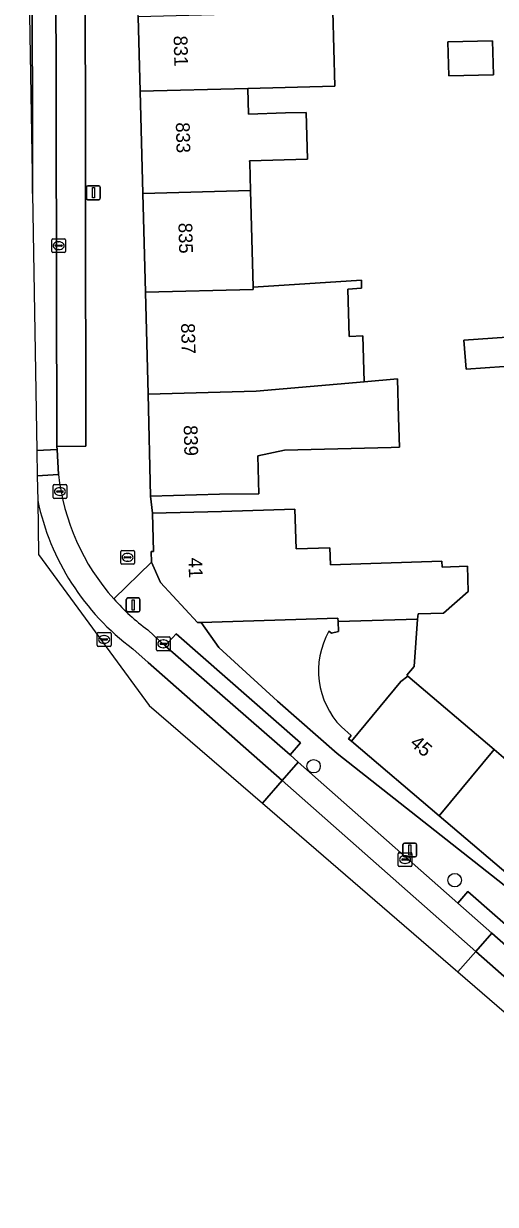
# Model space of a CAD drawing. Extents: x 162073 to 163043, y 381818 to 382561.
# Drawn here: x 162092.6 to 162126.8, y 382154 to 382239.5 of the extents above; entities that cross this region are included whole.
import ezdxf

# ---------------------------------------------------------------- set-up
doc = ezdxf.new("R2010")
doc.units = 0
for name, color, linetype in [('IMGEO_Boom', 7, 'Continuous'), ('IMGEO_Brandkraan', 7, 'Continuous'), ('IMGEO_Erf', 7, 'Continuous'), ('IMGEO_Kolk', 7, 'Continuous'), ('IMGEO_Lichtmast', 7, 'Continuous'), ('IMGEO_Pand', 7, 'Continuous'), ('IMGEO_Pand_nummerreeks', 7, 'Continuous'), ('IMGEO_Parkeervlak_open', 7, 'Continuous'), ('IMGEO_Rijbaan_lokaal_gesloten', 7, 'Continuous'), ('IMGEO_Rijbaan_lokaal_open', 7, 'Continuous'), ('IMGEO_Rioolput', 7, 'Continuous'), ('IMGEO_Voetpad_open', 7, 'Continuous')]:
    doc.layers.add(name, color=color, linetype=linetype)

msp = doc.modelspace()

# ---------------------------------------------------------------- linework, layer by layer
at = {"layer": 'IMGEO_Boom'}
for centre in [(162113.59, 382185.761), (162123.817, 382177.516)]:
    msp.add_circle(centre, 0.489, dxfattribs=at)
at = {"layer": 'IMGEO_Brandkraan'}
for p, q in [((162099.618, 382200.458), (162099.618, 382201.31)), ((162099.693, 382201.384), (162100.545, 382201.384)), ((162099.877, 382200.878), (162099.877, 382200.89)), ((162100.315, 382200.841), (162099.917, 382200.841)), ((162099.92, 382200.927), (162100.318, 382200.927)), ((162100.129, 382200.604), (162100.104, 382200.604)), ((162100.106, 382201.164), (162100.131, 382201.164)), ((162100.361, 382200.89), (162100.361, 382200.878)), ((162100.619, 382201.31), (162100.619, 382200.458)), ((162100.545, 382200.384), (162099.693, 382200.384))]:
    msp.add_line(p, q, dxfattribs=at)
for points in [[(162099.618, 382200.458), (162099.618, 382201.31)], [(162099.693, 382201.384), (162100.545, 382201.384)], [(162100.619, 382201.31), (162100.619, 382200.458)], [(162100.545, 382200.384), (162099.693, 382200.384)]]:
    msp.add_lwpolyline(points, dxfattribs=at)
for centre, radius, start, end in [((162099.695, 382201.308), 0.0765, 91.55205, 178.44795), ((162099.695, 382201.308), 0.0765, 91.55205, 178.44795), ((162099.917, 382200.887), 0.0403, 85.87752, 175.75265), ((162099.914, 382200.877), 0.0366, 178.93798, 274.71019), ((162100.318, 382200.884), 0.043, 264.86636, 352.45326), ((162100.322, 382200.889), 0.0386, 1.73085, 96.63898), ((162100.543, 382201.308), 0.0765, 1.55205, 88.44795), ((162100.543, 382201.308), 0.0765, 1.55205, 88.44795), ((162099.695, 382200.46), 0.0765, 181.55205, 268.44795), ((162099.695, 382200.46), 0.0765, 181.55205, 268.44795), ((162100.543, 382200.46), 0.0765, 271.55205, 358.44795), ((162100.543, 382200.46), 0.0765, 271.55205, 358.44795)]:
    msp.add_arc(centre, radius, start, end, dxfattribs=at)
for centre, major_axis, ratio, start_param, end_param in [((162100.105, 382200.884), (-0.387, 0.002), 0.722429, 4.712389, 7.853982), ((162100.13, 382200.884), (-0.39, 0.002), 0.717154, 1.570796, 4.712389)]:
    msp.add_ellipse(centre, major_axis=major_axis, ratio=ratio, start_param=start_param, end_param=end_param, dxfattribs=at)
at = {"layer": 'IMGEO_Erf'}
for points in [[(162114.982, 382240.388), (162115.121, 382234.987), (162108.82, 382234.834), (162108.873, 382232.978), (162111.548, 382233.054), (162113.051, 382233.097), (162113.148, 382229.701), (162108.958, 382229.582), (162108.961, 382229.475), (162109.019, 382227.44), (162109.22, 382220.433), (162117.054, 382220.951), (162117.069, 382220.362), (162116.079, 382220.309), (162116.159, 382216.882), (162117.159, 382216.908), (162117.245, 382213.599), (162119.68, 382213.815), (162119.753, 382211.001), (162119.809, 382208.856), (162119.208, 382208.841), (162111.491, 382208.642), (162109.564, 382208.226), (162109.636, 382205.482), (162106.786, 382205.446), (162101.788, 382205.303), (162101.912, 382204.071), (162106.91, 382204.214), (162112.238, 382204.367), (162112.32, 382201.493), (162114.769, 382201.573), (162114.81, 382200.334), (162122.886, 382200.599), (162122.9, 382200.172), (162124.742, 382200.233), (162124.802, 382198.405), (162123.009, 382196.852), (162121.156, 382196.796), (162121.126, 382196.404), (162120.867, 382192.984), (162120.336, 382192.358), (162120.417, 382192.289), (162126.683, 382186.968), (162128.881, 382185.102)], [(162114.707, 382195.536), (162114.894, 382195.385), (162115.389, 382195.506), (162115.361, 382196.228), (162115.351, 382196.472), (162105.452, 382196.17), (162106.723, 382194.356), (162110.979, 382190.462), (162115.288, 382186.678), (162128.205, 382176.536), (162128.654, 382177.108), (162122.692, 382182.171), (162116.33, 382187.574), (162116.118, 382187.754), (162116.308, 382187.99), (162115.612, 382188.605)]]:
    msp.add_lwpolyline(points, dxfattribs=at)
for points in [[(162126.619, 382235.824), (162123.389, 382235.74), (162123.326, 382238.193), (162126.556, 382238.277)], [(162128.77, 382214.806), (162124.636, 382214.51), (162124.487, 382216.597), (162128.621, 382216.892)]]:
    msp.add_lwpolyline(points, close=True, dxfattribs=at)
msp.add_arc((162119.709, 382192.665), 5.768, 150.14404, 224.73433, dxfattribs=at)
at = {"layer": 'IMGEO_Kolk'}
for p, q in [((162094.622, 382223.019), (162094.622, 382223.871)), ((162094.697, 382223.945), (162095.549, 382223.945)), ((162095.11, 382223.725), (162095.135, 382223.725)), ((162095.623, 382223.871), (162095.623, 382223.019)), ((162095.549, 382222.945), (162094.697, 382222.945)), ((162094.881, 382223.439), (162094.881, 382223.451)), ((162095.319, 382223.402), (162094.921, 382223.402)), ((162094.924, 382223.488), (162095.322, 382223.488)), ((162095.133, 382223.165), (162095.108, 382223.165)), ((162095.365, 382223.451), (162095.365, 382223.439)), ((162094.716, 382205.22), (162094.716, 382206.072)), ((162094.791, 382206.146), (162095.643, 382206.146)), ((162095.018, 382205.689), (162095.416, 382205.689)), ((162095.204, 382205.926), (162095.229, 382205.926)), ((162095.717, 382206.072), (162095.717, 382205.22)), ((162095.643, 382205.146), (162094.791, 382205.146)), ((162094.975, 382205.64), (162094.975, 382205.652)), ((162095.413, 382205.603), (162095.015, 382205.603)), ((162095.227, 382205.366), (162095.202, 382205.366)), ((162095.459, 382205.652), (162095.459, 382205.64)), ((162102.206, 382194.195), (162102.206, 382195.047)), ((162102.281, 382195.121), (162103.133, 382195.121)), ((162102.465, 382194.615), (162102.465, 382194.627)), ((162102.903, 382194.578), (162102.505, 382194.578)), ((162102.508, 382194.664), (162102.906, 382194.664)), ((162102.694, 382194.901), (162102.719, 382194.901)), ((162102.949, 382194.627), (162102.949, 382194.615)), ((162103.207, 382195.047), (162103.207, 382194.195)), ((162103.133, 382194.121), (162102.281, 382194.121)), ((162102.717, 382194.341), (162102.692, 382194.341)), ((162119.719, 382178.578), (162119.719, 382179.43)), ((162119.794, 382179.504), (162120.646, 382179.504)), ((162120.207, 382179.284), (162120.232, 382179.284)), ((162120.72, 382179.43), (162120.72, 382178.578)), ((162120.646, 382178.504), (162119.794, 382178.504)), ((162119.978, 382178.998), (162119.978, 382179.01)), ((162120.416, 382178.961), (162120.018, 382178.961)), ((162120.021, 382179.047), (162120.419, 382179.047)), ((162120.23, 382178.724), (162120.205, 382178.724)), ((162120.462, 382179.01), (162120.462, 382178.998))]:
    msp.add_line(p, q, dxfattribs=at)
for points in [[(162094.622, 382223.019), (162094.622, 382223.871)], [(162094.697, 382223.945), (162095.549, 382223.945)], [(162095.623, 382223.871), (162095.623, 382223.019)], [(162095.549, 382222.945), (162094.697, 382222.945)], [(162094.716, 382205.22), (162094.716, 382206.072)], [(162094.791, 382206.146), (162095.643, 382206.146)], [(162095.717, 382206.072), (162095.717, 382205.22)], [(162095.643, 382205.146), (162094.791, 382205.146)], [(162102.206, 382194.195), (162102.206, 382195.047)], [(162102.281, 382195.121), (162103.133, 382195.121)], [(162103.207, 382195.047), (162103.207, 382194.195)], [(162103.133, 382194.121), (162102.281, 382194.121)], [(162119.719, 382178.578), (162119.719, 382179.43)], [(162119.794, 382179.504), (162120.646, 382179.504)], [(162120.72, 382179.43), (162120.72, 382178.578)], [(162120.646, 382178.504), (162119.794, 382178.504)]]:
    msp.add_lwpolyline(points, dxfattribs=at)
for centre, radius, start, end in [((162094.699, 382223.869), 0.0765, 91.55205, 178.44795), ((162094.699, 382223.869), 0.0765, 91.55205, 178.44795), ((162095.547, 382223.869), 0.0765, 1.55205, 88.44795), ((162095.547, 382223.869), 0.0765, 1.55205, 88.44795), ((162094.699, 382223.021), 0.0765, 181.55205, 268.44795), ((162094.699, 382223.021), 0.0765, 181.55205, 268.44795), ((162094.921, 382223.448), 0.0403, 85.87752, 175.75265), ((162094.918, 382223.438), 0.0366, 178.93798, 274.71019), ((162095.322, 382223.445), 0.043, 264.86636, 352.45326), ((162095.326, 382223.45), 0.0386, 1.73085, 96.63898), ((162095.547, 382223.021), 0.0765, 271.55205, 358.44795), ((162095.547, 382223.021), 0.0765, 271.55205, 358.44795), ((162094.793, 382206.07), 0.0765, 91.55205, 178.44795), ((162094.793, 382206.07), 0.0765, 91.55205, 178.44795), ((162095.015, 382205.649), 0.0403, 85.87752, 175.75265), ((162095.42, 382205.651), 0.0386, 1.73085, 96.63898), ((162095.641, 382206.07), 0.0765, 1.55205, 88.44795), ((162095.641, 382206.07), 0.0765, 1.55205, 88.44795), ((162094.793, 382205.222), 0.0765, 181.55205, 268.44795), ((162094.793, 382205.222), 0.0765, 181.55205, 268.44795), ((162095.012, 382205.639), 0.0366, 178.93798, 274.71019), ((162095.416, 382205.646), 0.043, 264.86636, 352.45326), ((162095.641, 382205.222), 0.0765, 271.55205, 358.44795), ((162095.641, 382205.222), 0.0765, 271.55205, 358.44795), ((162102.283, 382195.045), 0.0765, 91.55205, 178.44795), ((162102.283, 382195.045), 0.0765, 91.55205, 178.44795), ((162102.505, 382194.624), 0.0403, 85.87752, 175.75265), ((162102.502, 382194.614), 0.0366, 178.93798, 274.71019), ((162102.906, 382194.621), 0.043, 264.86636, 352.45326), ((162102.91, 382194.626), 0.0386, 1.73085, 96.63898), ((162103.131, 382195.045), 0.0765, 1.55205, 88.44795), ((162103.131, 382195.045), 0.0765, 1.55205, 88.44795), ((162102.283, 382194.197), 0.0765, 181.55205, 268.44795), ((162102.283, 382194.197), 0.0765, 181.55205, 268.44795), ((162103.131, 382194.197), 0.0765, 271.55205, 358.44795), ((162103.131, 382194.197), 0.0765, 271.55205, 358.44795), ((162119.796, 382179.428), 0.0765, 91.55205, 178.44795), ((162119.796, 382179.428), 0.0765, 91.55205, 178.44795), ((162120.644, 382179.428), 0.0765, 1.55205, 88.44795), ((162120.644, 382179.428), 0.0765, 1.55205, 88.44795), ((162119.796, 382178.58), 0.0765, 181.55205, 268.44795), ((162119.796, 382178.58), 0.0765, 181.55205, 268.44795), ((162120.018, 382179.007), 0.0403, 85.87752, 175.75265), ((162120.015, 382178.997), 0.0366, 178.93798, 274.71019), ((162120.419, 382179.004), 0.043, 264.86636, 352.45326), ((162120.423, 382179.009), 0.0386, 1.73085, 96.63898), ((162120.644, 382178.58), 0.0765, 271.55205, 358.44795), ((162120.644, 382178.58), 0.0765, 271.55205, 358.44795)]:
    msp.add_arc(centre, radius, start, end, dxfattribs=at)
for centre, major_axis, ratio, start_param, end_param in [((162095.109, 382223.445), (-0.387, 0.002), 0.722429, 4.712389, 7.853982), ((162095.134, 382223.445), (-0.39, 0.002), 0.717154, 1.570796, 4.712389), ((162095.203, 382205.646), (-0.387, 0.002), 0.722429, 4.712389, 7.853982), ((162095.228, 382205.646), (-0.39, 0.002), 0.717154, 1.570796, 4.712389), ((162102.693, 382194.621), (-0.387, 0.002), 0.722429, 4.712389, 7.853982), ((162102.718, 382194.621), (-0.39, 0.002), 0.717154, 1.570796, 4.712389), ((162120.206, 382179.004), (-0.387, 0.002), 0.722429, 4.712389, 7.853982), ((162120.231, 382179.004), (-0.39, 0.002), 0.717154, 1.570796, 4.712389)]:
    msp.add_ellipse(centre, major_axis=major_axis, ratio=ratio, start_param=start_param, end_param=end_param, dxfattribs=at)
at = {"layer": 'IMGEO_Lichtmast'}
for p, q in [((162097.142, 382226.876), (162097.142, 382227.676)), ((162097.142, 382227.676), (162097.142, 382226.876)), ((162097.242, 382227.776), (162098.032, 382227.776)), ((162098.032, 382227.776), (162097.242, 382227.776)), ((162098.132, 382227.676), (162098.132, 382226.876)), ((162098.132, 382226.876), (162098.132, 382227.676)), ((162098.032, 382226.776), (162097.242, 382226.776)), ((162097.242, 382226.776), (162098.032, 382226.776)), ((162100.023, 382197.042), (162100.023, 382197.842)), ((162100.023, 382197.842), (162100.023, 382197.042)), ((162100.123, 382197.942), (162100.913, 382197.942)), ((162100.913, 382197.942), (162100.123, 382197.942)), ((162101.013, 382197.842), (162101.013, 382197.042)), ((162101.013, 382197.042), (162101.013, 382197.842)), ((162100.913, 382196.942), (162100.123, 382196.942)), ((162100.123, 382196.942), (162100.913, 382196.942)), ((162120.069, 382179.303), (162120.069, 382180.103)), ((162120.069, 382180.103), (162120.069, 382179.303)), ((162120.169, 382180.203), (162120.959, 382180.203)), ((162120.959, 382180.203), (162120.169, 382180.203)), ((162121.059, 382180.103), (162121.059, 382179.303)), ((162121.059, 382179.303), (162121.059, 382180.103)), ((162120.959, 382179.203), (162120.169, 382179.203)), ((162120.169, 382179.203), (162120.959, 382179.203))]:
    msp.add_line(p, q, dxfattribs=at)
for points in [[(162097.562, 382227.651), (162097.712, 382227.651), (162097.712, 382226.901), (162097.562, 382226.901), (162097.562, 382227.651)], [(162100.443, 382197.817), (162100.593, 382197.817), (162100.593, 382197.067), (162100.443, 382197.067), (162100.443, 382197.817)], [(162120.489, 382180.078), (162120.639, 382180.078), (162120.639, 382179.328), (162120.489, 382179.328), (162120.489, 382180.078)]]:
    msp.add_lwpolyline(points, dxfattribs=at)
for centre, start, end in [((162097.242, 382227.676), 90, 180), ((162097.242, 382227.676), 90, 180), ((162098.032, 382227.676), 0, 90), ((162098.032, 382227.676), 360, 90), ((162097.242, 382226.876), 180, 270), ((162097.242, 382226.876), 180, 270), ((162098.032, 382226.876), 270, 0), ((162098.032, 382226.876), 270, 0), ((162100.123, 382197.842), 90, 180), ((162100.123, 382197.842), 90, 180), ((162100.913, 382197.842), 0, 90), ((162100.913, 382197.842), 360, 90), ((162100.123, 382197.042), 180, 270), ((162100.123, 382197.042), 180, 270), ((162100.913, 382197.042), 270, 0), ((162100.913, 382197.042), 270, 0), ((162120.169, 382180.103), 90, 180), ((162120.169, 382180.103), 90, 180), ((162120.959, 382180.103), 0, 90), ((162120.959, 382180.103), 360, 90), ((162120.169, 382179.303), 180, 270), ((162120.169, 382179.303), 180, 270), ((162120.959, 382179.303), 270, 0), ((162120.959, 382179.303), 270, 0)]:
    msp.add_arc(centre, 0.1, start, end, dxfattribs=at)
at = {"layer": 'IMGEO_Pand'}
for points in [[(162108.82, 382234.834), (162115.121, 382234.987), (162114.982, 382240.388), (162114.674, 382240.38), (162100.891, 382240.002), (162101.03, 382234.622)], [(162126.619, 382235.824), (162126.556, 382238.277), (162123.326, 382238.193), (162123.389, 382235.74)], [(162113.051, 382233.097), (162111.548, 382233.054), (162108.873, 382232.978), (162108.82, 382234.834), (162101.03, 382234.622), (162101.221, 382227.228), (162109.019, 382227.44), (162108.961, 382229.475), (162108.958, 382229.582), (162113.148, 382229.701)], [(162109.019, 382227.44), (162101.221, 382227.228), (162101.406, 382220.07), (162109.224, 382220.283), (162109.22, 382220.433)], [(162117.159, 382216.908), (162116.159, 382216.882), (162116.079, 382220.309), (162117.069, 382220.362), (162117.054, 382220.951), (162109.22, 382220.433), (162109.224, 382220.283), (162101.406, 382220.07), (162101.597, 382212.694), (162109.441, 382212.907), (162117.245, 382213.599)], [(162124.636, 382214.51), (162128.77, 382214.806), (162128.621, 382216.892), (162124.487, 382216.597)], [(162119.753, 382211.001), (162119.68, 382213.815), (162117.245, 382213.599), (162109.441, 382212.907), (162101.597, 382212.694), (162101.788, 382205.303), (162106.786, 382205.446), (162109.636, 382205.482), (162109.564, 382208.226), (162111.491, 382208.642), (162119.208, 382208.841), (162119.809, 382208.856)], [(162122.886, 382200.599), (162114.81, 382200.334), (162114.769, 382201.573), (162112.32, 382201.493), (162112.238, 382204.367), (162106.91, 382204.214), (162101.912, 382204.071), (162101.99, 382201.313), (162101.832, 382201.309), (162101.855, 382200.535), (162102.489, 382199.064), (162105.192, 382196.162), (162105.452, 382196.17), (162115.351, 382196.472), (162115.361, 382196.228), (162121.126, 382196.404), (162121.156, 382196.796), (162123.009, 382196.852), (162124.802, 382198.405), (162124.742, 382200.233), (162122.9, 382200.172)], [(162116.33, 382187.574), (162122.692, 382182.171), (162126.683, 382186.968), (162120.417, 382192.289), (162119.922, 382191.893)], [(162122.692, 382182.171), (162128.654, 382177.108), (162132.693, 382181.866), (162128.881, 382185.102), (162126.683, 382186.968)]]:
    msp.add_lwpolyline(points, close=True, dxfattribs=at)
msp.add_lwpolyline([(162115.612, 382188.605), (162116.308, 382187.99), (162116.118, 382187.754), (162116.33, 382187.574), (162119.922, 382191.893), (162120.417, 382192.289), (162120.336, 382192.358), (162120.867, 382192.984), (162121.126, 382196.404), (162115.361, 382196.228), (162115.389, 382195.506), (162114.894, 382195.385), (162114.707, 382195.536)], dxfattribs=at)
msp.add_arc((162119.709, 382192.665), 5.768, 150.14404, 224.73433, dxfattribs=at)
at = {"layer": 'IMGEO_Parkeervlak_open'}
for points in [[(162094.896, 382256.77), (162095.001, 382208.911)], [(162095.001, 382208.911), (162097.085, 382208.93), (162097.038, 382245.779)]]:
    msp.add_lwpolyline(points, dxfattribs=at)
at = {"layer": 'IMGEO_Rijbaan_lokaal_gesloten'}
for points in [[(162093.544, 382208.615), (162095.014, 382208.683), (162095.001, 382208.911), (162094.896, 382256.77), (162094.884, 382264.048), (162093.177, 382264.048), (162093.226, 382227.227)], [(162112.473, 382186.067), (162111.312, 382184.731), (162125.354, 382172.361), (162126.507, 382173.673), (162124.041, 382175.842)], [(162180.708, 382125.942), (162167.996, 382137.104), (162167.885, 382137.201), (162167.101, 382137.877), (162163.514, 382141.043), (162162.557, 382141.907), (162133.933, 382167.137), (162132.408, 382168.485), (162126.507, 382173.673), (162125.354, 382172.361), (162179.272, 382124.864), (162197.645, 382110.646), (162198.731, 382112.02), (162198.53, 382112.194)]]:
    msp.add_lwpolyline(points, close=True, dxfattribs=at)
for points in [[(162095.114, 382206.885), (162093.575, 382206.795), (162093.606, 382205.009)], [(162100.495, 382194.267), (162101.615, 382193.273), (162111.312, 382184.731), (162112.473, 382186.067), (162111.891, 382186.581), (162102.844, 382194.469), (162102.427, 382194.84), (162101.573, 382195.633)]]:
    msp.add_lwpolyline(points, dxfattribs=at)
for centre, radius, start, end in [((162111.188, 382208.632), 16.169, 186.20126, 221.72725), ((162111.15, 382208.68), 17.924, 191.81777, 233.52627), ((162111.195, 382208.642), 16.181, 221.73864, 233.51193)]:
    msp.add_arc(centre, radius, start, end, dxfattribs=at)
at = {"layer": 'IMGEO_Rijbaan_lokaal_open'}
for points in [[(162093.226, 382227.227), (162093.177, 382264.048), (162094.884, 382264.048), (162094.885, 382264.932), (162093.137, 382264.876), (162092.582, 382264.872), (162092.784, 382253.072), (162093.226, 382227.227)], [(162093.575, 382206.795), (162095.114, 382206.885), (162095.014, 382208.683), (162093.544, 382208.615), (162093.575, 382206.795)], [(162093.606, 382205.009), (162093.673, 382201.086), (162101.683, 382190.161), (162109.883, 382183.088)], [(162109.883, 382183.088), (162111.312, 382184.731), (162101.615, 382193.273), (162100.495, 382194.267)], [(162124.046, 382170.871), (162125.354, 382172.361), (162111.312, 382184.731), (162109.883, 382183.088), (162124.046, 382170.871)], [(162196.622, 382109.326), (162197.645, 382110.646), (162179.272, 382124.864), (162125.354, 382172.361), (162124.046, 382170.871), (162166.369, 382134.365), (162181.661, 382121.174), (162196.622, 382109.326)]]:
    msp.add_lwpolyline(points, dxfattribs=at)
msp.add_arc((162111.15, 382208.68), 17.924, 191.81777, 233.52627, dxfattribs=at)
at = {"layer": 'IMGEO_Rioolput'}
for p, q in [((162097.991, 382195.44), (162098.843, 382195.44)), ((162097.916, 382194.514), (162097.916, 382195.366)), ((162098.175, 382194.934), (162098.175, 382194.946)), ((162098.613, 382194.897), (162098.215, 382194.897)), ((162098.218, 382194.983), (162098.616, 382194.983)), ((162098.427, 382194.66), (162098.402, 382194.66)), ((162098.404, 382195.22), (162098.429, 382195.22)), ((162098.659, 382194.946), (162098.659, 382194.934)), ((162098.917, 382195.366), (162098.917, 382194.514)), ((162098.843, 382194.44), (162097.991, 382194.44))]:
    msp.add_line(p, q, dxfattribs=at)
for points in [[(162097.991, 382195.44), (162098.843, 382195.44)], [(162097.916, 382194.514), (162097.916, 382195.366)], [(162098.917, 382195.366), (162098.917, 382194.514)], [(162098.843, 382194.44), (162097.991, 382194.44)]]:
    msp.add_lwpolyline(points, dxfattribs=at)
for centre, radius, start, end in [((162097.993, 382195.364), 0.0765, 91.55205, 178.44795), ((162097.993, 382195.364), 0.0765, 91.55205, 178.44795), ((162098.841, 382195.364), 0.0765, 1.55205, 88.44795), ((162098.841, 382195.364), 0.0765, 1.55205, 88.44795), ((162098.215, 382194.943), 0.0403, 85.87752, 175.75265), ((162098.212, 382194.933), 0.0366, 178.93798, 274.71019), ((162098.616, 382194.94), 0.043, 264.86636, 352.45326), ((162098.62, 382194.945), 0.0386, 1.73085, 96.63898), ((162097.993, 382194.516), 0.0765, 181.55205, 268.44795), ((162097.993, 382194.516), 0.0765, 181.55205, 268.44795), ((162098.841, 382194.516), 0.0765, 271.55205, 358.44795), ((162098.841, 382194.516), 0.0765, 271.55205, 358.44795)]:
    msp.add_arc(centre, radius, start, end, dxfattribs=at)
for centre, major_axis, ratio, start_param, end_param in [((162098.403, 382194.94), (-0.387, 0.002), 0.722429, 4.712389, 7.853982), ((162098.428, 382194.94), (-0.39, 0.002), 0.717154, 1.570796, 4.712389)]:
    msp.add_ellipse(centre, major_axis=major_axis, ratio=ratio, start_param=start_param, end_param=end_param, dxfattribs=at)
at = {"layer": 'IMGEO_Voetpad_open'}
for points in [[(162099.121, 382197.87), (162101.855, 382200.535), (162101.832, 382201.309), (162101.99, 382201.313), (162101.912, 382204.071), (162101.788, 382205.303), (162101.597, 382212.694), (162101.406, 382220.07), (162101.221, 382227.228), (162101.03, 382234.622), (162100.891, 382240.002), (162100.737, 382245.969), (162100.633, 382250), (162100.463, 382256.572), (162100.29, 382263.285), (162100.136, 382269.243), (162099.774, 382283.238), (162101.824, 382283.276), (162101.939, 382286.02), (162101.97, 382292.535), (162101.962, 382297.689), (162101.954, 382300.039), (162101.931, 382301.562), (162101.986, 382343.468)], [(162095.392, 382280.819), (162096.753, 382279.402), (162096.994, 382278.768), (162097.009, 382249.05), (162098.084, 382249.034), (162098.088, 382245.76), (162097.038, 382245.779), (162097.085, 382208.93), (162095.001, 382208.911), (162095.014, 382208.683), (162095.114, 382206.885)], [(162128.205, 382176.536), (162115.288, 382186.678), (162110.979, 382190.462), (162106.723, 382194.356), (162105.452, 382196.17), (162105.192, 382196.162), (162102.489, 382199.064), (162101.855, 382200.535), (162099.121, 382197.87)], [(162101.573, 382195.633), (162102.427, 382194.84), (162102.844, 382194.469), (162103.636, 382195.347), (162112.645, 382187.461), (162111.891, 382186.581), (162112.473, 382186.067), (162124.041, 382175.842), (162124.776, 382176.701), (162133.164, 382169.342), (162132.408, 382168.485), (162133.933, 382167.137)]]:
    msp.add_lwpolyline(points, dxfattribs=at)
for points in [[(162111.891, 382186.581), (162112.645, 382187.461), (162103.636, 382195.347), (162102.844, 382194.469)], [(162124.776, 382176.701), (162124.041, 382175.842), (162126.507, 382173.673), (162132.408, 382168.485), (162133.164, 382169.342)]]:
    msp.add_lwpolyline(points, close=True, dxfattribs=at)
for centre, radius, start, end in [((162111.188, 382208.632), 16.169, 186.20126, 221.72725), ((162111.195, 382208.642), 16.181, 221.73864, 233.51193)]:
    msp.add_arc(centre, radius, start, end, dxfattribs=at)

# ---------------------------------------------------------------- texts
at = {"layer": 'IMGEO_Pand_nummerreeks'}
for s, rotation, p in [('831', 271.48023, (162103.448, 382238.642)), ('833', 271.47802, (162103.61, 382232.368)), ('835', 271.47802, (162103.798, 382225.092)), ('837', 271.47802, (162103.986, 382217.825)), ('839', 271.47802, (162104.177, 382210.442)), ('41', 271.62126, (162104.524, 382200.855)), ('45', 319.66094, (162120.512, 382187.328))]:
    msp.add_text(s, height=1, rotation=rotation, dxfattribs=at).set_placement(p)

doc.saveas('drawing.dxf')
